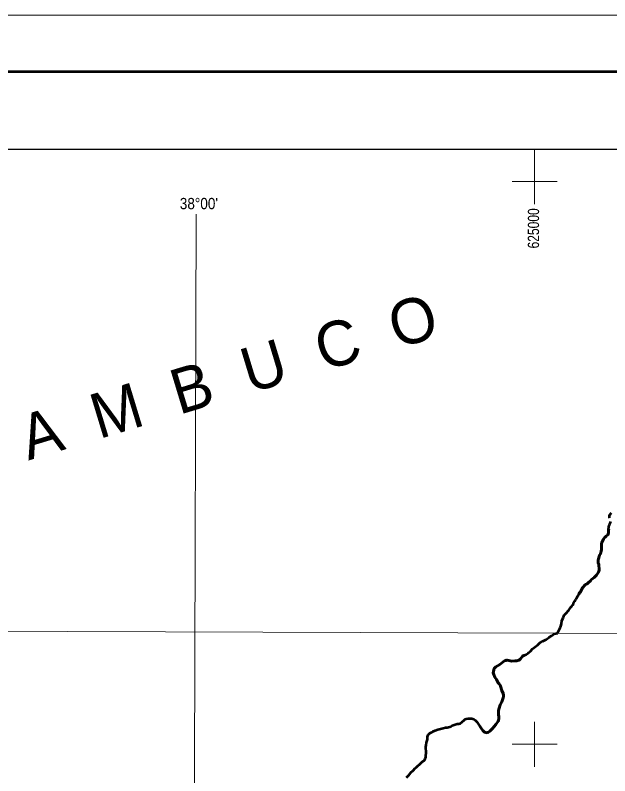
# Model space of a CAD drawing. Extents: x 553962 to 842807, y 8883888 to 9032388.
# Drawn here: x 601949 to 628336, y 8998597 to 9032388 of the extents above; entities that cross this region are included whole.
import ezdxf
from ezdxf.enums import TextEntityAlignment as Align

# ---------------------------------------------------------------- set-up
doc = ezdxf.new("R2010")
doc.units = 0
doc.header["$LTSCALE"] = 200
doc.linetypes.add('LONG_DASH_SHORT_DASH', pattern=[9.9, 6, -1.2, 1.5, -1.2])
for name, color, linetype, lineweight in [('1', 7, 'Continuous', 13), ('2', 7, 'Continuous', 13), ('24', 7, 'Continuous', 25), ('3', 7, 'Continuous', 13), ('7', 7, 'Continuous', 90)]:
    doc.layers.add(name, color=color, linetype=linetype, lineweight=lineweight)
for name, color, linetype in [('42', 7, 'Continuous'), ('46', 7, 'Continuous'), ('47', 7, 'Continuous')]:
    doc.layers.add(name, color=color, linetype=linetype)

msp = doc.modelspace()

# ---------------------------------------------------------------- linework, layer by layer
at = {"layer": '1'}
for points in [[(609971.9, 9023551.8), (609764.7, 8949706.7), (609734.2, 8939404.4)], [(565303.2, 9005146.6), (664889.8, 9004806.7), (719872.1, 9004543.9), (790635.8, 9004109)]]:
    msp.add_lwpolyline(points, dxfattribs=at)
at = {"layer": '2'}
for p, q in [((625000, 9024000), (625000, 9026438.8)), ((624000, 9025000), (626000, 9025000)), ((625000, 8999000), (625000, 9001000)), ((624000, 9000000), (626000, 9000000))]:
    msp.add_line(p, q, dxfattribs=at)
at = {"layer": '24', "lineweight": 53}
for points in [[(628342.8, 9010045.3), (628316.9, 9010072.4), (628323, 9010177.8), (628415.6, 9010283.4)], [(626725, 9006288.4), (626779.1, 9006348.8), (626820, 9006414.7), (626852.1, 9006473.1), (626884.2, 9006537.2), (626914.5, 9006591.8), (626995.8, 9006730.4), (627000.8, 9006736), (627018.2, 9006741.7), (627022, 9006744.6), (627030, 9006769), (627091.7, 9006889.6), (627130.8, 9006942.4), (627168.5, 9006999), (627205.7, 9007042.3), (627264.5, 9007088.6), (627330, 9007129.3), (627383.4, 9007169.9), (627473.6, 9007266.1), (627521.8, 9007311.4), (627580.8, 9007360.5), (627647.4, 9007407.8), (627691, 9007452.1), (627741.2, 9007505), (627838.2, 9007649.2), (627862.8, 9007736.7), (627868.9, 9007802.6), (627855.6, 9007930.4), (627843.1, 9007991.5), (627825.9, 9008062.9), (627820.1, 9008114.6), (627823, 9008171.1), (627839.1, 9008232.2), (627861.6, 9008347.1), (627883.5, 9008403.6), (627919.6, 9008464.8), (627956.3, 9008575), (627969.5, 9008644.6), (627969.3, 9008703.9), (627962.7, 9008772.5), (627963, 9008898.5), (627984.8, 9008964.4), (628013.5, 9009025.6), (628060.6, 9009104.8), (628119, 9009194.3), (628125.3, 9009200.9), (628181.5, 9009242.5), (628249.4, 9009298.2), (628267.2, 9009335.9), (628279.4, 9009398.9), (628279.5, 9009462.9), (628282.4, 9009525), (628295.3, 9009656.7), (628310.9, 9009719.8), (628332.7, 9009781.9), (628390, 9009900.6)], [(626161, 9005249.2), (626188.6, 9005351.8), (626211.6, 9005488.2), (626262, 9005622), (626290.8, 9005686), (626318.1, 9005740.6), (626357.2, 9005784), (626440.5, 9005861.4), (626481.1, 9005905.8), (626516.3, 9005951), (626547.5, 9005998.1), (626576.5, 9006046.2), (626606.6, 9006087.7), (626651.3, 9006133.9), (626697.2, 9006185.8), (626721.1, 9006227.2), (626725, 9006288.4)], [(626020.3, 9004931.6), (626138.4, 9005165.4), (626161, 9005249.2)], [(624968.7, 9004287.4), (625077.4, 9004367.4), (625125.3, 9004407.4), (625196.1, 9004475.4), (625232, 9004503.4), (625369.3, 9004583.4), (625507, 9004648.4), (625552.2, 9004680.4), (625627.3, 9004743.4), (625747.5, 9004813.4), (625804.8, 9004859.3), (625863.6, 9004898.3), (625936.5, 9004925.7), (626020.3, 9004931.6)], [(622356.1, 9001071.6), (622438.9, 9000988.6), (622501.2, 9000910.6), (622651.6, 9000673.6), (622694.8, 9000613.6), (622741.9, 9000562.6), (622781.6, 9000528.6), (622838, 9000513.6), (622887.5, 9000510.6), (622903.5, 9000513.6), (622951.5, 9000538.6), (623008.3, 9000580.6), (623061.1, 9000626.5), (623124.5, 9000694.5), (623279.2, 9000880.5), (623385, 9001031.5), (623398.2, 9001059.5), (623411.2, 9001147.5), (623406.1, 9001224.5), (623394.5, 9001300.5), (623396.9, 9001485.5), (623407.8, 9001557.5), (623420.7, 9001604.5), (623474.8, 9001753.5), (623546.5, 9001882.5), (623566.5, 9001928.5), (623606.4, 9002057.5), (623614.4, 9002114.5), (623615.2, 9002180.5), (623603.6, 9002252.5), (623548.9, 9002380.5), (623488.7, 9002579.5), (623465.3, 9002623.5), (623431.2, 9002675.5), (623387.3, 9002730.5), (623302, 9002882.5), (623235.1, 9002973.5), (623183.3, 9003094.5), (623167.7, 9003160.5), (623170, 9003229.5), (623186.6, 9003301.5), (623210, 9003362.5), (623241.9, 9003412.5), (623274.8, 9003442.5), (623462.1, 9003547.5), (623608.8, 9003667.5), (623666.2, 9003700.5), (623727.2, 9003726.5), (623755.6, 9003733.5), (623782.5, 9003731.5), (623993.5, 9003691.5), (624127.2, 9003701.5), (624209, 9003698.5), (624301.4, 9003736.4), (624324.7, 9003751.4), (624377.4, 9003798.4), (624433, 9003873.4), (624469.5, 9003912.4), (624514.8, 9003941.4), (624628.9, 9003992.4), (624709.5, 9004038.4), (624743.9, 9004077.4), (624810.6, 9004137.4), (624900.3, 9004230.4), (624968, 9004288.4)], [(620148.3, 8999353.7), (620168.6, 8999417.7), (620186.8, 8999678.7), (620178.1, 8999819.7), (620178.5, 8999880.7), (620194.3, 8999957.7), (620208.2, 9000078.7), (620242.8, 9000202.7), (620252.9, 9000329.7), (620263.2, 9000378.7), (620280.1, 9000412.7), (620305.3, 9000447.7), (620344.5, 9000485.7), (620432.6, 9000539.7), (620488.9, 9000569.7), (620581.6, 9000610.7), (620710.5, 9000657.7), (620939.4, 9000718.7), (621042.2, 9000740.6), (621118.4, 9000748.6), (621242.2, 9000776.6), (621275.5, 9000790.6), (621342.1, 9000826.6), (621518.2, 9000894.6), (621561.1, 9000901.6), (621637.2, 9000903.6), (621689.6, 9000916.6), (621716.6, 9000931.6), (621774.6, 9000977.6), (621867.2, 9001066.6), (621924.7, 9001110.6), (621967.5, 9001129.6), (622048.6, 9001140.6), (622160.3, 9001143.6), (622215.2, 9001136.6), (622300.1, 9001105.6), (622356.1, 9001071.6)], [(619310.3, 8998518.8), (619402.8, 8998610.8), (619472.9, 8998704.8), (619501.7, 8998736.7), (619608.1, 8998826.7), (619700.3, 8998928.7), (619746.9, 8998966.7), (619804.3, 8999021.7), (619907.6, 8999106.7), (619970.1, 8999177.7), (620010.3, 8999215.7), (620083.8, 8999267.7), (620109.1, 8999292.7), (620148.3, 8999353.7), (620148.3, 8999353.7)]]:
    msp.add_lwpolyline(points, dxfattribs=at)
at = {"layer": '3'}
msp.add_lwpolyline([(842807.3, 9032387.8), (842807.3, 8883887.8), (553961.7, 8883887.8), (553961.7, 9032387.8)], close=True, dxfattribs=at)
at = {"layer": '3', "lineweight": 53}
msp.add_lwpolyline([(840307.3, 9029887.8), (840307.3, 8886387.8), (560211.7, 8886387.8), (560211.7, 9029887.8)], close=True, dxfattribs=at)
at = {"layer": '3', "lineweight": 25}
msp.add_lwpolyline([(563033.9, 9026438.8), (793061.1, 9026438.8), (793495.6, 8889836.8), (563468.3, 8889836.8)], close=True, dxfattribs=at)
at = {"layer": '7', "linetype": 'LONG_DASH_SHORT_DASH', "lineweight": 60}
for points in [[(626960, 9006669.3), (626995.8, 9006730.4), (627000.8, 9006736), (627018.2, 9006741.7), (627022, 9006744.6), (627030, 9006769), (627091.7, 9006889.6), (627130.8, 9006942.4), (627168.5, 9006999), (627205.7, 9007042.3), (627264.5, 9007088.6), (627330, 9007129.3), (627383.4, 9007169.9), (627473.6, 9007266.1), (627521.8, 9007311.4), (627580.8, 9007360.5), (627647.4, 9007407.8), (627691, 9007452.1), (627741.2, 9007505), (627838.2, 9007649.2), (627862.8, 9007736.7), (627868.9, 9007802.6), (627855.6, 9007930.4), (627843.1, 9007991.5), (627825.9, 9008062.9), (627820.1, 9008114.6), (627823, 9008171.1), (627839.1, 9008232.2), (627861.6, 9008347.1), (627883.5, 9008403.6), (627919.6, 9008464.8), (627956.3, 9008575), (627969.5, 9008644.6), (627969.3, 9008703.9), (627962.7, 9008772.5), (627963, 9008898.5), (627984.8, 9008964.4), (628013.5, 9009025.6), (628060.6, 9009104.8), (628119, 9009194.3), (628125.3, 9009200.9), (628181.5, 9009242.5), (628249.4, 9009298.2), (628267.2, 9009335.9), (628279.4, 9009398.9), (628279.5, 9009462.9), (628282.4, 9009525), (628286.6, 9009568.2)], [(622572.2, 9000798.7), (622651.6, 9000673.6), (622694.8, 9000613.6), (622741.9, 9000562.6), (622781.6, 9000528.6), (622838, 9000513.6), (622887.5, 9000510.6), (622903.5, 9000513.6), (622951.5, 9000538.6), (623008.3, 9000580.6), (623061.1, 9000626.5), (623124.5, 9000694.5), (623279.2, 9000880.5), (623385, 9001031.5), (623398.2, 9001059.5), (623411.2, 9001147.5), (623406.1, 9001224.5), (623394.5, 9001300.5), (623396.9, 9001485.5), (623407.8, 9001557.5), (623420.7, 9001604.5), (623474.8, 9001753.5), (623546.5, 9001882.5), (623566.5, 9001928.5), (623606.4, 9002057.5), (623614.4, 9002114.5), (623615.2, 9002180.5), (623603.6, 9002252.5), (623548.9, 9002380.5), (623488.7, 9002579.5), (623465.3, 9002623.5), (623431.2, 9002675.5), (623387.3, 9002730.5), (623302, 9002882.5), (623235.1, 9002973.5), (623183.3, 9003094.5), (623167.7, 9003160.5), (623170, 9003229.5), (623186.6, 9003301.5), (623210, 9003362.5), (623241.9, 9003412.5), (623274.8, 9003442.5), (623462.1, 9003547.5), (623608.8, 9003667.5), (623666.2, 9003700.5), (623727.2, 9003726.5), (623755.6, 9003733.5), (623782.5, 9003731.5), (623993.5, 9003691.5), (624127.2, 9003701.5), (624209, 9003698.5), (624301.4, 9003736.4), (624324.7, 9003751.4), (624377.4, 9003798.4), (624433, 9003873.4), (624469.5, 9003912.4), (624514.8, 9003941.4)]]:
    msp.add_lwpolyline(points, dxfattribs=at)

# ---------------------------------------------------------------- texts
at = {"layer": '42'}
msp.add_text('P  E  R  N  A  M  B  U  C  O', height=2000, rotation=16.855, dxfattribs=at).set_placement((589730.9, 9008723.5))
at = {"layer": '46', "width": 0.9}
msp.add_text("38°00'", height=500, dxfattribs=at).set_placement((610099.9, 9023770.4), align=Align.CENTER)
at = {"layer": '47', "width": 0.8}
msp.add_text('625000', height=500, rotation=90, dxfattribs=at).set_placement((625197.3, 9022917.4), align=Align.CENTER)

doc.saveas('drawing.dxf')
